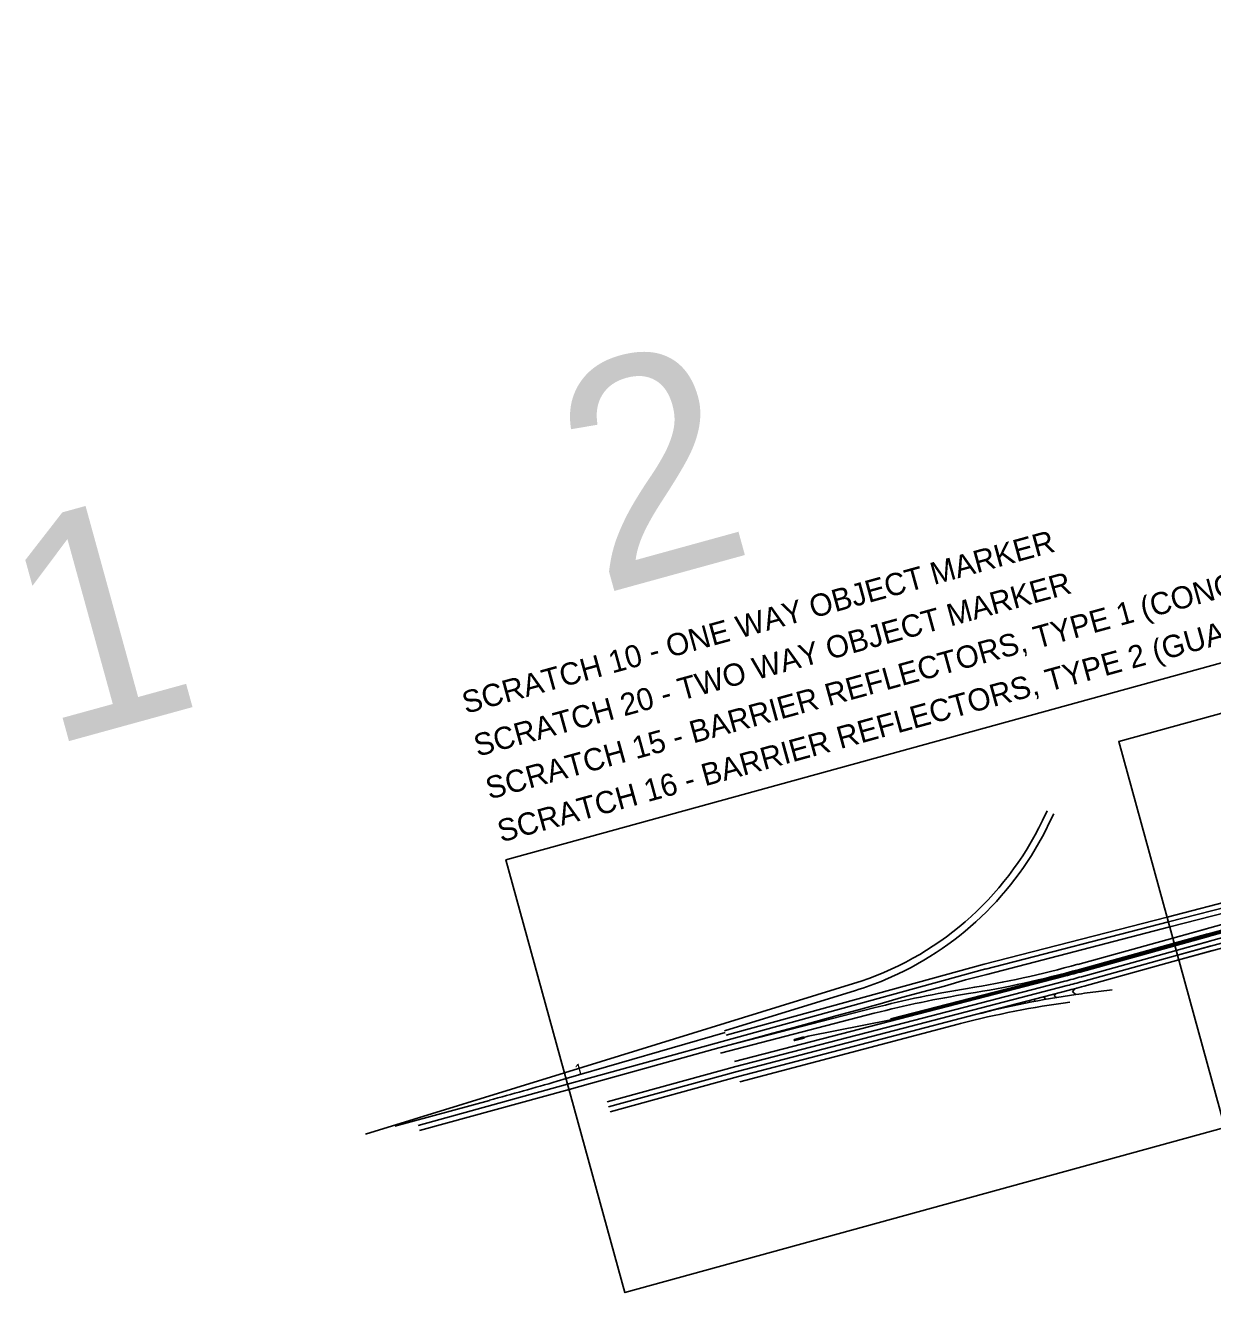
# Model space of a CAD drawing. Extents: x 2129512 to 2138277, y 657615 to 661243.
# Drawn here: x 2129512 to 2132183, y 657615 to 660465 of the extents above; entities that cross this region are included whole.
import ezdxf

# ---------------------------------------------------------------- set-up
doc = ezdxf.new("R2010")
doc.units = 0
for name, color, linetype in [('BR_P_Slab_Object', 7, 'Continuous'), ('BR_X_SV_Abut_Text', 7, 'Continuous'), ('GE_X_Alignment_100_Stations', 7, 'Continuous'), ('MT_P_CL_50', 7, 'Continuous'), ('MT_P_Dotted_Line', 7, 'Continuous'), ('MT_P_Drums', 7, 'Continuous'), ('MT_P_Gore_Marking', 7, 'Continuous'), ('MT_P_PCB', 7, 'Continuous'), ('MT_P_Temp_Road', 7, 'Continuous'), ('MT_P_Traffic_Attenuator', 7, 'Continuous'), ('MT_P_Work_Area', 7, 'Continuous'), ('MT_X_Dotted_Line', 7, 'Continuous'), ('MT_X_Drums', 7, 'Continuous'), ('MT_X_Edge_Line', 7, 'Continuous'), ('MT_X_Gore_Marking', 7, 'Continuous'), ('MT_X_Traffic_Attenuator', 7, 'Continuous'), ('PV_P_Shoulder', 7, 'Continuous'), ('SC_Scratch1', 7, 'Continuous')]:
    doc.layers.add(name, color=color, linetype=linetype)

msp = doc.modelspace()

# ---------------------------------------------------------------- linework, layer by layer
at = {"layer": 'BR_P_Slab_Object'}
msp.add_lwpolyline([(2131649.8, 658240.3), (2131116.6, 658101.1), (2130827.6, 658021.6)], dxfattribs=at)
at = {"layer": 'BR_X_SV_Abut_Text'}
for p, q in [((2131086.3, 658199.8), (2130728.8, 658096.3)), ((2130728.8, 658096.3), (2130708.8, 658090.5)), ((2130556.3, 658047.5), (2130343.4, 657989.2))]:
    msp.add_line(p, q, dxfattribs=at)
msp.add_arc((2127719.7, 668409.3), 10743, 285.30992, 286.15495, dxfattribs=at)
at = {"layer": 'GE_X_Alignment_100_Stations'}
for p, q in [((2131811, 658698.8), (2131800.7, 658677.1)), ((2131825.8, 658691.7), (2131815.1, 658670.2)), ((2131375.4, 658310), (2130725.2, 658109.3)), ((2130725.2, 658109.3), (2130277.7, 657971.2))]:
    msp.add_line(p, q, dxfattribs=at)
for radius, start in [(700, 287.1493), (716, 292.7154)]:
    msp.add_arc((2131169, 658978.9), radius, start, 334.4653, dxfattribs=at)
at = {"layer": 'MT_P_CL_50'}
for p, q in [((2131855.9, 658305.5), (2131113.5, 658112.4)), ((2131085.2, 658203.7), (2131380.2, 658294.7)), ((2131860.8, 658295.4), (2131649.8, 658240.3)), ((2131510.1, 658227.3), (2131110.4, 658123.9)), ((2131110.4, 658123.9), (2130821.1, 658044.4)), ((2131113.5, 658112.4), (2130824.3, 658032.8))]:
    msp.add_line(p, q, dxfattribs=at)
for centre, radius, start, end in [((2131169, 658978.9), 716, 287.1493, 292.7154), ((2131270.5, 660556.6), 2326, 284.5757, 285.4723), ((2132159, 656289.6), 2016, 98.0791, 104.6303), ((2131270.5, 660556.6), 2337, 284.6301, 285.0512)]:
    msp.add_arc(centre, radius, start, end, dxfattribs=at)
at = {"layer": 'MT_P_Dotted_Line'}
for p, q in [((2132863.9, 658661.3), (2132080.8, 658459.6)), ((2132866.7, 658650.7), (2132083.8, 658448.9)), ((2132869.6, 658640), (2132086.9, 658437.4)), ((2132080.8, 658459.6), (2131669.2, 658353.6)), ((2132083.8, 658448.9), (2131672.2, 658342.8)), ((2132086.9, 658437.4), (2131675.5, 658330.8)), ((2132093.8, 658412.5), (2132169.5, 658433.5)), ((2132097, 658400.9), (2132172.7, 658421.9)), ((2131880.4, 658353.4), (2132093.8, 658412.5)), ((2131883.6, 658341.9), (2132097, 658400.9)), ((2131885.2, 658336.1), (2132098.6, 658395.2)), ((2132098.6, 658395.2), (2132174.3, 658416.1)), ((2132101.5, 658384.5), (2132177.2, 658405.5)), ((2132104.4, 658373.9), (2132180.1, 658394.9)), ((2131888.1, 658325.5), (2132101.5, 658384.5)), ((2131891.1, 658314.9), (2132104.4, 658373.9)), ((2131894, 658304.3), (2132107.3, 658363.3)), ((2132107.3, 658363.3), (2132183, 658384.3)), ((2131673.3, 658343.1), (2130780.4, 658097.1)), ((2131669.2, 658353.6), (2131429.2, 658288)), ((2131847.2, 658325.9), (2131107.4, 658134.7)), ((2131850.5, 658315.4), (2131510.1, 658227.3)), ((2131088.9, 658193.8), (2131429.2, 658288)), ((2131072.7, 658165.4), (2131420.9, 658255.3)), ((2131076, 658153.6), (2131422.2, 658243.2)), ((2131072.7, 658165.4), (2130783.6, 658085.5))]:
    msp.add_line(p, q, dxfattribs=at)
for points in [[(2131419.2, 658260.3), (2131435, 658264.6), (2131483, 658278.9), (2131531.4, 658291.7), (2131579.8, 658304.5), (2131627.6, 658318.3), (2131675.5, 658330.8)], [(2131072.7, 658165.4), (2131098, 658172.3), (2131145.3, 658185.4), (2131194.1, 658198.4), (2131242.1, 658211.2), (2131290.4, 658225), (2131338.4, 658238.2), (2131386.5, 658251.4), (2131419.2, 658260.3)]]:
    msp.add_lwpolyline(points, dxfattribs=at)
for centre, radius, start, end in [((2131270.5, 660556.6), 2286, 279.0967, 285.4723), ((2131270.5, 660556.6), 2298, 279.0967, 285.4723), ((2131270.5, 660556.6), 2304, 284.4948, 285.4723), ((2131270.5, 660556.6), 2315, 284.5082, 285.4723), ((2131270.5, 660556.6), 2337, 284.9224, 285.4723), ((2131995.3, 656030.2), 2298, 99.0967, 104.4754), ((2131995.3, 656030.2), 2286, 99.0967, 104.5184)]:
    msp.add_arc(centre, radius, start, end, dxfattribs=at)
at = {"layer": 'MT_P_Drums'}
for p, q in [((2131804.2, 658277.5), (2131806.3, 658281.1)), ((2131826.8, 658282.4), (2131829.6, 658287.2)), ((2131868.2, 658291.3), (2131872.3, 658298.4)), ((2131736, 658261.8), (2131736.7, 658263)), ((2131747.4, 658264.5), (2131748.3, 658266)), ((2131758.8, 658267.2), (2131759.9, 658269)), ((2131770.2, 658269.8), (2131771.5, 658272.1)), ((2131781.5, 658272.4), (2131783.1, 658275.1))]:
    msp.add_line(p, q, dxfattribs=at)
for centre, start, end in [((2130652.4, 656622.9), 55.0276, 55.1587), ((2130656.5, 656640.9), 54.3429, 54.516), ((2130664.6, 656673.9), 53.0791, 53.3459), ((2130641.5, 656568.8), 57.078, 57.1182), ((2130643.2, 656577.8), 56.7365, 56.7883), ((2130644.9, 656586.8), 56.395, 56.4597), ((2130646.7, 656595.9), 56.0533, 56.1324), ((2130648.6, 656604.9), 55.7116, 55.8065)]:
    msp.add_arc(centre, 2016, start, end, dxfattribs=at)
at = {"layer": 'MT_P_Gore_Marking'}
for p, q in [((2131459.2, 658228.7), (2131273.5, 658191.6)), ((2131273.5, 658191.6), (2131263.9, 658188.9))]:
    msp.add_line(p, q, dxfattribs=at)
at = {"layer": 'MT_P_PCB'}
for p, q in [((2132863.9, 658661.3), (2132080.8, 658459.6)), ((2132869.6, 658640), (2132086.9, 658437.4)), ((2132080.8, 658459.6), (2131669.2, 658353.6)), ((2132086.9, 658437.4), (2131675.5, 658330.8)), ((2132093.8, 658412.5), (2132208.9, 658444.4)), ((2132097, 658400.9), (2132212, 658432.8)), ((2132098.6, 658395.2), (2132213.6, 658427)), ((2131880.4, 658353.4), (2132093.8, 658412.5)), ((2131883.6, 658341.9), (2132097, 658400.9)), ((2131885.2, 658336.1), (2132098.6, 658395.2)), ((2132107.3, 658363.3), (2132222.4, 658395.2)), ((2131894, 658304.3), (2132107.3, 658363.3)), ((2131669.2, 658353.6), (2131429.2, 658288)), ((2131847.2, 658325.9), (2131107.4, 658134.7)), ((2131957.6, 658295.8), (2131926.8, 658292.2)), ((2131076, 658153.6), (2131422.2, 658243.2)), ((2131610.6, 658218.7), (2131119.9, 658089.3)), ((2131610.6, 658218.7), (2131615.8, 658220))]:
    msp.add_line(p, q, dxfattribs=at)
msp.add_lwpolyline([(2131419.2, 658260.3), (2131435, 658264.6), (2131483, 658278.9), (2131531.4, 658291.7), (2131579.8, 658304.5), (2131627.6, 658318.3), (2131675.5, 658330.8)], dxfattribs=at)
for centre, radius, start, end in [((2131270.5, 660556.6), 2286, 279.0967, 285.4723), ((2131270.5, 660556.6), 2298, 279.0967, 285.4723), ((2131270.5, 660556.6), 2304, 284.4948, 285.4723), ((2131270.5, 660556.6), 2337, 284.9224, 285.4723), ((2131995.3, 656030.2), 2298, 99.0967, 104.4754), ((2131995.3, 656030.2), 2286, 99.0967, 104.5184), ((2132159, 656289.6), 2016, 96.6141, 98.0791), ((2132121, 656284.9), 2000, 97.432, 104.6303)]:
    msp.add_arc(centre, radius, start, end, dxfattribs=at)
at = {"layer": 'MT_P_Temp_Road'}
for p, q in [((2132097.8, 658398), (2132212.8, 658429.9)), ((2131884.4, 658339), (2132097.8, 658398)), ((2131846.5, 658328.8), (2131459.2, 658228.7)), ((2131459.2, 658228.7), (2131273.5, 658191.6)), ((2131273.5, 658191.6), (2131263.9, 658188.9))]:
    msp.add_line(p, q, dxfattribs=at)
msp.add_arc((2131270.5, 660556.6), 2301, 284.4948, 285.4723, dxfattribs=at)
at = {"layer": 'MT_P_Work_Area'}
for p, q in [((2132866.7, 658650.7), (2132083.8, 658448.9)), ((2132083.8, 658448.9), (2131672.2, 658342.8)), ((2132101.5, 658384.5), (2132216.5, 658416.4)), ((2132104.4, 658373.9), (2132219.5, 658405.8)), ((2131888.1, 658325.5), (2132101.5, 658384.5)), ((2131891.1, 658314.9), (2132104.4, 658373.9)), ((2131673.3, 658343.1), (2130780.4, 658097.1)), ((2131850.5, 658315.4), (2131510.1, 658227.3)), ((2131088.9, 658193.8), (2131429.2, 658288)), ((2131072.7, 658165.4), (2131420.9, 658255.3)), ((2131072.7, 658165.4), (2130783.6, 658085.5))]:
    msp.add_line(p, q, dxfattribs=at)
msp.add_lwpolyline([(2131072.7, 658165.4), (2131098, 658172.3), (2131145.3, 658185.4), (2131194.1, 658198.4), (2131242.1, 658211.2), (2131290.4, 658225), (2131338.4, 658238.2), (2131386.5, 658251.4), (2131419.2, 658260.3)], dxfattribs=at)
msp.add_arc((2131270.5, 660556.6), 2315, 284.5082, 285.4723, dxfattribs=at)
at = {"layer": 'MT_X_Dotted_Line'}
for p, q in [((2132097.8, 658398), (2132212.8, 658429.9)), ((2131884.4, 658339), (2132097.8, 658398)), ((2131846.5, 658328.8), (2131459.2, 658228.7))]:
    msp.add_line(p, q, dxfattribs=at)
msp.add_arc((2131270.5, 660556.6), 2301, 284.4948, 285.4723, dxfattribs=at)
at = {"layer": 'MT_X_Edge_Line'}
for p, q in [((2130732.2, 658083.8), (2130395.9, 657991.3)), ((2130780.4, 658097.1), (2130732.2, 658083.8)), ((2130783.6, 658085.5), (2130735.4, 658072.2)), ((2130735.4, 658072.2), (2130399, 657980))]:
    msp.add_line(p, q, dxfattribs=at)
at = {"layer": 'MT_X_Gore_Marking'}
for p, q in [((2132097.2, 658400), (2132212.3, 658431.8)), ((2132098.3, 658396.1), (2132213.4, 658428)), ((2131883.9, 658340.9), (2132097.2, 658400)), ((2131884.9, 658337.1), (2132098.3, 658396.1)), ((2131846, 658330.8), (2131458.7, 658230.7)), ((2131847, 658326.9), (2131459.7, 658226.8)), ((2131459.2, 658228.7), (2131273.5, 658191.6)), ((2131273.5, 658191.6), (2131263.9, 658188.9))]:
    msp.add_line(p, q, dxfattribs=at)
for radius in [2299, 2303]:
    msp.add_arc((2131270.5, 660556.6), radius, 284.4948, 285.4723, dxfattribs=at)
at = {"layer": 'MT_X_Traffic_Attenuator'}
for p, q in [((2130732.2, 658083.8), (2130395.9, 657991.3)), ((2130780.4, 658097.1), (2130732.2, 658083.8)), ((2130783.6, 658085.5), (2130735.4, 658072.2)), ((2130735.4, 658072.2), (2130399, 657980))]:
    msp.add_line(p, q, dxfattribs=at)
at = {"layer": 'PV_P_Shoulder'}
msp.add_lwpolyline([(2134910.7, 658729.4), (2134671.9, 659597.2), (2136054.1, 659967.1), (2136234.4, 659083.8), (2137570.2, 659277.9), (2137491.7, 660175.9), (2137412.1, 660465.2), (2130593.3, 658588.4), (2130861.2, 657615), (2132211, 657986.5), (2131972.2, 658854.2), (2133322, 659225.7), (2133560.8, 658358)], close=True, dxfattribs=at)
at = {"layer": 'SC_Scratch1'}
for p, q in [((2131263.5, 658190.1), (2131242.8, 658184.4)), ((2131244.3, 658182.2), (2131242.8, 658184.4)), ((2131264.2, 658187.7), (2131243.5, 658182)), ((2131243.5, 658182), (2131243.7, 658184.6)), ((2131246.1, 658182.7), (2131244.5, 658184.9)), ((2131245.2, 658182.5), (2131245.4, 658185.1)), ((2131247.8, 658183.2), (2131246.3, 658185.4)), ((2131246.9, 658183), (2131247.1, 658185.6)), ((2131249.5, 658183.7), (2131248, 658185.8)), ((2131248.7, 658183.4), (2131248.9, 658186.1)), ((2131251.3, 658184.1), (2131249.7, 658186.3)), ((2131250.4, 658183.9), (2131250.6, 658186.6)), ((2131253, 658184.6), (2131251.5, 658186.8)), ((2131252.1, 658184.4), (2131252.3, 658187)), ((2131254.7, 658185.1), (2131253.2, 658187.3)), ((2131253.9, 658184.9), (2131254.1, 658187.5)), ((2131256.5, 658185.6), (2131254.9, 658187.7)), ((2131255.6, 658185.3), (2131255.8, 658188)), ((2131258.2, 658186.1), (2131256.7, 658188.2)), ((2131257.3, 658185.8), (2131257.5, 658188.5)), ((2131259.9, 658186.5), (2131258.4, 658188.7)), ((2131259.1, 658186.3), (2131259.3, 658188.9)), ((2131261.7, 658187), (2131260.1, 658189.2)), ((2131260.8, 658186.8), (2131261, 658189.4)), ((2131263.4, 658187.5), (2131261.9, 658189.7)), ((2131262.5, 658187.2), (2131262.7, 658189.9)), ((2131263.5, 658190.1), (2131264.2, 658187.7))]:
    msp.add_line(p, q, dxfattribs=at)
msp.add_arc((2131243.1, 658183.2), 1.25, 105.3886, 285.3886, dxfattribs=at)

# ---------------------------------------------------------------- texts
at = {"layer": 'MT_P_Gore_Marking'}
msp.add_text('SCRATCH 10 - ONE WAY OBJECT MARKER', height=50, rotation=15.3886, dxfattribs=at).set_placement((2130503, 658916.6))
at = {"layer": 'MT_P_Traffic_Attenuator'}
for s, p in [('2', (2130804.9, 659184.2)), ('1', (2129561.3, 658841.9))]:
    msp.add_text(s, height=500, rotation=15.3872, dxfattribs=at).set_placement(p)
at = {"layer": 'MT_X_Dotted_Line'}
msp.add_text('SCRATCH 20 - TWO WAY OBJECT MARKER', height=50, rotation=15.3886, dxfattribs=at).set_placement((2130529.5, 658820.2))
at = {"layer": 'MT_X_Drums'}
msp.add_text('SCRATCH 16 - BARRIER REFLECTORS, TYPE 2 (GUARDRAIL)', height=50, rotation=15.3886, dxfattribs=at).set_placement((2130582.6, 658627.4))
at = {"layer": 'MT_X_Gore_Marking'}
msp.add_text('SCRATCH 15 - BARRIER REFLECTORS, TYPE 1 (CONCRETE BARRIER)', height=50, rotation=15.3886, dxfattribs=at).set_placement((2130556.1, 658723.8))
at = {"layer": 'MT_X_Traffic_Attenuator'}
msp.add_text('1', height=25, rotation=15.3886, dxfattribs=at).set_placement((2130752.5, 658102.8))

doc.saveas('drawing.dxf')
